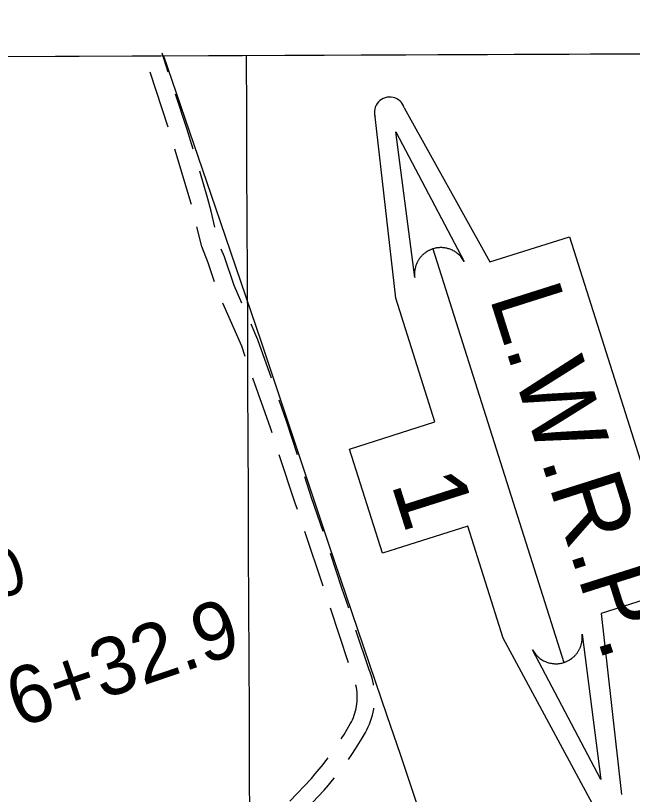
# Model space of a CAD drawing. Extents: x 3419139 to 3457078, y 540382 to 565875.
# Drawn here: x 3438619 to 3439688, y 562745 to 564093 of the extents above; entities that cross this region are included whole.
import ezdxf

# ---------------------------------------------------------------- set-up
doc = ezdxf.new("R2010")
doc.units = 0
for name, color, linetype in [('V-GRID-FRAM', 7, 'Continuous'), ('V-GRID-MAJR', 7, 'Continuous'), ('V-RIVR-RANG-IDEN', 7, 'Continuous'), ('V-ROAD-CNTR', 7, 'Continuous'), ('V-SITE-OTLN', 7, 'Continuous'), ('V-SURV-IDEN', 7, 'Continuous'), ('V-TOPO-WATR-IDEN', 7, 'Continuous'), ('V-UTIL-LINE', 7, 'Continuous')]:
    doc.layers.add(name, color=color, linetype=linetype)

msp = doc.modelspace()

# ---------------------------------------------------------------- linework, layer by layer
at = {"layer": 'V-GRID-FRAM'}
msp.add_lwpolyline([(3423200.915, 563955.0750000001), (3454837.934, 564093.122), (3454925.2090000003, 545910.191), (3423272.322, 545772.075), (3423200.915, 563955.0750000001)], dxfattribs=at)
at = {"layer": 'V-GRID-MAJR'}
msp.add_spline([(3439098.765, 545841.133), (3439072.333, 551898.653), (3439045.886, 557959.642), (3439019.4390000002, 564020.648), (3439019.424, 564024.098)], degree=3, dxfattribs=at)
at = {"layer": 'V-ROAD-CNTR'}
for p, q in [((3438884.005144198, 563995.0417323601), (3438873.0824069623, 564028.103282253)), ((3438883.742295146, 563900.2043415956), (3438852.3723724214, 563995.1565722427)), ((3439152.145508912, 563105.0944458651), (3439120.2856041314, 563199.8832577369)), ((3439196.3400550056, 562972.2534711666), (3439164.8030902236, 563067.1500858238))]:
    msp.add_line(p, q, dxfattribs=at)
for points in [[(3438926.918704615, 563861.7923936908), (3438916.1749916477, 563897.6682449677), (3438896.5531132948, 563957.0608400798)], [(3438924.147609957, 563766.1686407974), (3438923.6772927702, 563768.0434054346), (3438895.5436647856, 563861.9883811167)], [(3438964.597830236, 563727.0025890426), (3438958.0634137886, 563754.2651748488), (3438952.6107072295, 563776.0005945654), (3438938.3939573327, 563823.4737545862)], [(3438964.046435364, 563632.2177724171), (3438952.90480815, 563665.0134938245), (3438941.848628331, 563693.2060871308), (3438933.6721008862, 563727.3198114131)], [(3439011.2776287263, 563595.2772281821), (3438997.8353410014, 563626.0218154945), (3438981.08719185, 563675.3205061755), (3438975.837562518, 563688.7067451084)], [(3439017.408037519, 563502.8794644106), (3439011.1376928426, 563520.7109181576), (3438978.64930552, 563595.016875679)], [(3439062.4983669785, 563465.0869349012), (3439039.0703071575, 563531.7110818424), (3439027.301850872, 563558.6273582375)], [(3439063.6758494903, 563370.7478171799), (3439060.7807713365, 563379.5371384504), (3439030.6773404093, 563465.1445434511)], [(3439107.816117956, 563332.6322130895), (3439089.1812286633, 563389.2068615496), (3439075.7676699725, 563427.3520136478)], [(3439107.5416422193, 563237.7987824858), (3439103.8321830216, 563248.8350750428), (3439076.1898047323, 563332.7560369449)], [(3439151.9700112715, 563199.7786921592), (3439132.2978169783, 563258.3069249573), (3439120.3300734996, 563294.6404319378)], [(3439196.4547421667, 563067.0345872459), (3439184.8204766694, 563102.0427884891), (3439164.7139731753, 563161.8631674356)], [(3439239.584138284, 562933.925229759), (3439239.3235377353, 562935.5201323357), (3439238.218961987, 562940.8086726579), (3439236.8867120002, 562946.04665638), (3439235.324849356, 562951.2217493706), (3439233.5388028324, 562956.3249020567), (3439231.8179138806, 562960.6246869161), (3439209.069527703, 563029.0759425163)], [(3439183.623784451, 562840.9620909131), (3439188.4267968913, 562848.5544561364), (3439193.914473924, 562857.6031816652), (3439199.1802750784, 562866.6644503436), (3439201.1610181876, 562870.3410893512), (3439202.9412425, 562874.0273427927), (3439204.5594442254, 562877.7859135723), (3439206.0104320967, 562881.6138316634), (3439207.2964522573, 562885.5038054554), (3439208.4082488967, 562889.4403061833), (3439209.346751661, 562893.4235566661), (3439210.1121011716, 562897.4513486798), (3439210.7014379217, 562901.5008848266), (3439211.110401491, 562905.570718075), (3439211.341529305, 562909.6594380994), (3439211.3949896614, 562913.7543289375), (3439211.2691967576, 562917.8451831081), (3439210.9639660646, 562921.9295836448), (3439210.4821120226, 562925.9947422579), (3439209.822462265, 562930.0318676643), (3439208.985038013, 562934.041327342), (3439208.9180542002, 562934.3046864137)], [(3439195.887590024, 562805.3591945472), (3439201.839902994, 562814.0287204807), (3439207.9730940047, 562823.3372587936), (3439213.9312031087, 562832.7555438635), (3439219.7115260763, 562842.2868183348), (3439225.361724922, 562852.0095496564), (3439227.886981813, 562856.6969106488), (3439230.2387575, 562861.5666572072), (3439232.376555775, 562866.5320864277), (3439234.2915679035, 562871.5841683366), (3439235.987547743, 562876.7141945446), (3439237.4577511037, 562881.9196938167), (3439238.697248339, 562887.1804433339), (3439239.705898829, 562892.4886513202), (3439239.9412829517, 562894.1060568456)], [(3439094.680506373, 562733.2292538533), (3439131.815035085, 562772.3425885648), (3439138.6146879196, 562780.1898123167), (3439145.3958723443, 562788.3153487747), (3439152.022792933, 562796.567832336), (3439158.492521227, 562804.9428284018), (3439160.837472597, 562808.0988672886)], [(3439104.2645109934, 562699.7524949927), (3439154.040964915, 562752.1814114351), (3439161.4693120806, 562760.7541876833), (3439168.6101276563, 562769.3106512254), (3439171.8762318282, 562773.3779205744)]]:
    msp.add_lwpolyline(points, dxfattribs=at)
at = {"layer": 'V-SITE-OTLN'}
msp.add_line((3437902.535471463, 564019.2249947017), (3440568.1845515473, 564030.8564590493), dxfattribs=at)
at = {"layer": 'V-TOPO-WATR-IDEN'}
msp.add_line((3439342.348199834, 563689.2407376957), (3439569.089130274, 562973.0773551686), dxfattribs=at)
for points in [[(3439292.7786504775, 563933.6515597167), (3439441.002740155, 563666.5682475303), (3439578.9777109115, 563710.251211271), (3439771.7087161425, 563101.5000521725), (3439633.7337453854, 563057.8170884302), (3439669.2105617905, 562744.6712912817)], [(3439618.65867963, 562728.666533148), (3439464.250568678, 563015.282406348), (3439402.8518564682, 563209.2135134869), (3439254.76650928, 563162.329598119), (3439197.6986347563, 563342.5815234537), (3439345.783981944, 563389.4654388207), (3439277.9214667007, 563603.8128125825), (3439242.2267683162, 563917.6468015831)]]:
    msp.add_lwpolyline(points, dxfattribs=at)
for points in [[(3439310.7672079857, 563639.907625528), (3439278.2399837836, 563891.7349268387), (3439396.5700914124, 563667.071299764), (3439394.2318497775, 563670.9929418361), (3439391.613684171, 563674.5364575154), (3439390.4652980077, 563675.8925842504), (3439389.41206716, 563677.0475500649), (3439388.07999541, 563678.3974434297), (3439386.744533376, 563679.6487137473), (3439385.547221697, 563680.6872612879), (3439383.8522842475, 563682.0402747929), (3439381.962055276, 563683.4038344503), (3439380.8756457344, 563684.1219093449), (3439379.446352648, 563685.0036221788), (3439377.5148508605, 563686.0850665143), (3439375.9785862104, 563686.8573897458), (3439374.293790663, 563687.6267426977), (3439373.1670635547, 563688.0944723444), (3439371.914829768, 563688.5759614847), (3439370.366920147, 563689.1117373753), (3439368.926279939, 563689.5571776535), (3439367.4749115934, 563689.952019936), (3439366.277173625, 563690.2415026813), (3439364.4829104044, 563690.6111734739), (3439362.751419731, 563690.8968748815), (3439361.3599084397, 563691.0778074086), (3439359.717571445, 563691.2359701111), (3439358.2872059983, 563691.3259322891), (3439357.01692764, 563691.3674550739), (3439356.030790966, 563691.3762135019), (3439354.5222203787, 563691.345439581), (3439352.976347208, 563691.2635210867), (3439351.5161769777, 563691.13950739), (3439350.0348155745, 563690.963156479), (3439348.6682824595, 563690.7570782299), (3439347.1821725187, 563690.4863943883), (3439345.9699345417, 563690.2253228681), (3439344.24755307, 563689.7964460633), (3439342.348199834, 563689.2407376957), (3439341.7460809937, 563689.045386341), (3439340.8705372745, 563688.7445879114), (3439339.8381638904, 563688.3626694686), (3439338.8459972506, 563687.9730265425), (3439337.8939655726, 563687.5709162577), (3439336.9735603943, 563687.1583649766), (3439335.8979212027, 563686.6447449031), (3439335.1559839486, 563686.2698160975), (3439334.0832489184, 563685.6973269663), (3439333.0965537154, 563685.13634428), (3439332.4225405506, 563684.7357188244), (3439330.72059274, 563683.6509175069), (3439329.831349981, 563683.0405458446), (3439329.2285019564, 563682.6089563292), (3439328.247730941, 563681.8752038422), (3439327.3916605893, 563681.1998122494), (3439326.514399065, 563680.4720834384), (3439325.4999418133, 563679.5813413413), (3439324.574218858, 563678.7234127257), (3439323.8707541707, 563678.0381210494), (3439323.2800750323, 563677.438885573), (3439322.495638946, 563676.6068078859), (3439321.8075898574, 563675.8430075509), (3439321.0338982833, 563674.9372358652), (3439320.2691899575, 563673.9981204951), (3439319.5253579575, 563673.0278534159), (3439318.6158893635, 563671.7707117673), (3439317.9914188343, 563670.8508216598), (3439317.329237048, 563669.8214424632), (3439316.7068810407, 563668.7905116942), (3439316.2235097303, 563667.9467613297), (3439315.7170147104, 563667.0170208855), (3439315.007000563, 563665.6169136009), (3439314.98151927, 563665.5632181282), (3439314.583066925, 563664.7196056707), (3439314.300768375, 563664.0905597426), (3439313.8940393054, 563663.1389102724), (3439313.417701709, 563661.9449492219), (3439313.0639779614, 563660.9849071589), (3439312.7637897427, 563660.1141900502), (3439312.4037879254, 563658.9901020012), (3439312.085544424, 563657.8981152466), (3439311.874427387, 563657.1138132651), (3439311.6197517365, 563656.0844334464), (3439311.3077800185, 563654.6545818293), (3439311.145946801, 563653.8040672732), (3439311.0295272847, 563653.133135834), (3439310.9305333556, 563652.5164961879), (3439310.824477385, 563651.7780436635), (3439310.7025581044, 563650.8064284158), (3439310.602398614, 563649.8306886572), (3439310.5222596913, 563648.8612874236), (3439310.463118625, 563647.9001075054), (3439310.420071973, 563646.654520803), (3439310.4092544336, 563645.9084596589), (3439310.4177389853, 563644.713802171), (3439310.465585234, 563643.3302137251), (3439310.529659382, 563642.2979070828), (3439310.593319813, 563641.5203573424), (3439310.663490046, 563640.796790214), (3439310.721993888, 563640.2740691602)], [(3439600.670122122, 563022.4104673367), (3439633.1973463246, 562770.5831660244), (3439514.867238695, 562995.2467930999), (3439517.2054803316, 562991.3251510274), (3439519.8236459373, 562987.7816353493), (3439520.9720321, 562986.4255086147), (3439522.025262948, 562985.2705428), (3439523.3573346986, 562983.9206494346), (3439524.6927967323, 562982.6693791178), (3439525.8901084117, 562981.6308315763), (3439527.585045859, 562980.2778180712), (3439529.475274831, 562978.9142584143), (3439530.5616843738, 562978.1961835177), (3439531.990977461, 562977.3144706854), (3439533.922479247, 562976.2330263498), (3439535.4587438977, 562975.4607031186), (3439537.143539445, 562974.6913501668), (3439538.270266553, 562974.2236205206), (3439539.5225003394, 562973.7421313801), (3439541.070409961, 562973.2063554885), (3439542.511050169, 562972.7609152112), (3439543.9624185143, 562972.3660729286), (3439545.160156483, 562972.0765901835), (3439546.9544197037, 562971.7069193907), (3439548.685910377, 562971.4212179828), (3439550.077421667, 562971.2402854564), (3439551.7197586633, 562971.0821227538), (3439553.1501241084, 562970.9921605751), (3439554.4204024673, 562970.9506377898), (3439555.406539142, 562970.9418793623), (3439556.9151097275, 562970.9726532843), (3439558.4609828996, 562971.0545717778), (3439559.9211531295, 562971.1785854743), (3439561.402514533, 562971.3549363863), (3439562.7690476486, 562971.5610146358), (3439564.25515759, 562971.8316984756), (3439565.467395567, 562972.0927699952), (3439567.1897770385, 562972.521646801), (3439569.089130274, 562973.0773551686), (3439569.6912491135, 562973.2727065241), (3439570.566792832, 562973.5735049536), (3439571.599166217, 562973.9554233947), (3439572.591332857, 562974.3450663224), (3439573.5433645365, 562974.7471766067), (3439574.4637697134, 562975.1597278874), (3439575.539408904, 562975.6733479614), (3439576.281346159, 562976.0482767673), (3439577.35408119, 562976.6207658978), (3439578.340776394, 562977.1817485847), (3439579.0147895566, 562977.5823740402), (3439580.716737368, 562978.6671753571), (3439581.6059801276, 562979.2775470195), (3439582.2088281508, 562979.7091365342), (3439583.189599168, 562980.442889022), (3439584.0456695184, 562981.1182806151), (3439584.9229310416, 562981.8460094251), (3439585.9373882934, 562982.7367515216), (3439586.863111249, 562983.5946801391), (3439587.5665759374, 562984.2799718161), (3439588.1572550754, 562984.8792072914), (3439588.941691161, 562985.711284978), (3439589.6297402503, 562986.4750853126), (3439590.403431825, 562987.3808569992), (3439591.168140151, 562988.3199723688), (3439591.9119721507, 562989.2902394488), (3439592.8214407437, 562990.5473810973), (3439593.4459112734, 562991.4672712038), (3439594.108093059, 562992.4966504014), (3439594.730449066, 562993.5275811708), (3439595.2138203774, 562994.3713315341), (3439595.720315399, 562995.301071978), (3439596.430329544, 562996.7011792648), (3439596.455810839, 562996.7548747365), (3439596.854263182, 562997.5984871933), (3439597.1365617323, 562998.2275331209), (3439597.543290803, 562999.1791825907), (3439598.019628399, 563000.3731436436), (3439598.3733521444, 563001.3331857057), (3439598.673540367, 563002.2039028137), (3439599.033542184, 563003.3279908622), (3439599.3517856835, 563004.4199776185), (3439599.5629027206, 563005.2042795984), (3439599.81757837, 563006.2336594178), (3439600.12955009, 563007.6635110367), (3439600.2913833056, 563008.5140255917), (3439600.407802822, 563009.1849570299), (3439600.506796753, 563009.8015966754), (3439600.6128527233, 563010.5400492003), (3439600.7347720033, 563011.5116644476), (3439600.8349314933, 563012.4874042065), (3439600.9150704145, 563013.4568054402), (3439600.974211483, 563014.417985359), (3439601.0172581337, 563015.6635720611), (3439601.028075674, 563016.4096332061), (3439601.019591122, 563017.604290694), (3439600.971744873, 563018.9878791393), (3439600.907670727, 563020.0201857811), (3439600.844010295, 563020.7977355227), (3439600.7738400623, 563021.5213026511), (3439600.71533622, 563022.0440237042)]]:
    msp.add_lwpolyline(points, close=True, dxfattribs=at)
msp.add_arc((3439267.5027093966, 563925.6491806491), 26.51247382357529, 17.5678203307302, 197.5678203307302, dxfattribs=at)
at = {"layer": 'V-UTIL-LINE'}
msp.add_lwpolyline([(3438875.831639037, 564023.471937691), (3438965.075, 563761.866), (3439044.654, 563528.1190000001), (3439161.276, 563178.554), (3439262.432, 562881.373), (3439285.366, 562814.49), (3439375.705, 562544.899)], dxfattribs=at)

# ---------------------------------------------------------------- texts
at = {"layer": 'V-RIVR-RANG-IDEN'}
msp.add_text('D-010', height=83.00000000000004, rotation=17.773325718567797, dxfattribs=at).set_placement((3438356.480813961, 563007.4598870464))
at = {"layer": 'V-SURV-IDEN'}
msp.add_text('3476+32.9', height=100, rotation=18.81333335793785, dxfattribs=at).set_placement((3438413.8077212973, 562787.6348176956))
at = {"layer": 'V-TOPO-WATR-IDEN'}
for s, height, rotation, p in [('L.W.R.P.', 124.49949299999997, 287.5677559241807, (3439439.6468385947, 563605.5552607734)), ('1', 124.50014099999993, 287.56786019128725, (3439269.477907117, 563283.3002833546))]:
    msp.add_text(s, height=height, rotation=rotation, dxfattribs=at).set_placement(p)

doc.saveas('drawing.dxf')
